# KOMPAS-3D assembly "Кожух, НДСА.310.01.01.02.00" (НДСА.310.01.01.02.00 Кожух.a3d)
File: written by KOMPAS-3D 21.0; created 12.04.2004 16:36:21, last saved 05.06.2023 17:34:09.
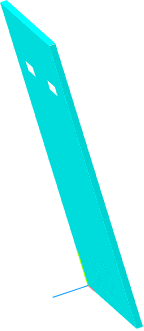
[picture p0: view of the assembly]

Document properties: Полное имя файла: C:\PLM\НДСА.310.01.01.02.00 Кожух.a3d

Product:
- Part/product: Кожух  | designation НДСА.310.01.01.02.00
    Масса: 6.188608
    additional columns: <item xmlns="http://appius.ru/pdm" xmlns:xs="http://www.w3.org/2001/XMLSchema" x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; <item xmlns="http://appius.ru/pdm" xmlns:xs="http://www.w3.org/2001/XMLSchema" x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; <item xmlns="http://appius.ru/pdm" xmlns:xs="http://www.w3.org/2001/XMLSchema" x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; <item xmlns="http://appius.ru/pdm" xmlns:xs="http://www.w3.org/2001/XMLSchema" x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; <item xmlns="http://appius.ru/pdm" xmlns:xs="http://www.w3.org/2001/XMLSchema" x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; <item xmlns="http://appius.ru/pdm" xmlns:xs="http://www.w3.org/2001/XMLSchema" x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; <item xmlns="http://appius.ru/pdm" xmlns:xs="http://www.w3.org/2001/XMLSchema" x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; <item xmlns="http://appius.ru/pdm" xmlns:xs="http://www.w3.org/2001/XMLSchema" x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
    source file: НДСА.310.01.01.02.00 Кожух.spw
  - Component [detail]: Крышка  | designation НДСА.310.01.01.02.01  | pos. 1  | Масса: 5.766009; Раздел спецификации: Детали; Форматы листов документа: A2; additional columns: <item xmlns="http://appius.ru/pdm" xmlns:xs="http://www.w3.org/2001/XMLSchema" x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; <item xmlns="http://appius.ru/pdm" xmlns:xs="http://www.w3.org/2001/XMLSchema" x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; <item xmlns="http://appius.ru/pdm" xmlns:xs="http://www.w3.org/2001/XMLSchema" x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; <item xmlns="http://appius.ru/pdm" xmlns:xs="http://www.w3.org/2001/XMLSchema" x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; <item xmlns="http://appius.ru/pdm" xmlns:xs="http://www.w3.org/2001/XMLSchema" x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; <item xmlns="http://appius.ru/pdm" xmlns:xs="http://www.w3.org/2001/XMLSchema" x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; <item xmlns="http://appius.ru/pdm" xmlns:xs="http://www.w3.org/2001/XMLSchema" x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; <item xmlns="http://appius.ru/pdm" xmlns:xs="http://www.w3.org/2001/XMLSchema" x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; source file: НДСА.310.01.01.02.01 Крышка.CDW, НДСА.310.01.01.02.01 Крышка.m3d
  - Component [detail]: Стяжка  | designation НДСА.875.03.00.00.02  | pos. 2  | Масса: 0.4226; Раздел спецификации: Детали; Форматы листов документа: A4; additional columns: <item xmlns="http://appius.ru/pdm" xmlns:xs="http://www.w3.org/2001/XMLSchema" x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; <item xmlns="http://appius.ru/pdm" xmlns:xs="http://www.w3.org/2001/XMLSchema" x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; <item xmlns="http://appius.ru/pdm" xmlns:xs="http://www.w3.org/2001/XMLSchema" x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; <item xmlns="http://appius.ru/pdm" xmlns:xs="http://www.w3.org/2001/XMLSchema" x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; <item xmlns="http://appius.ru/pdm" xmlns:xs="http://www.w3.org/2001/XMLSchema" x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; <item xmlns="http://appius.ru/pdm" xmlns:xs="http://www.w3.org/2001/XMLSchema" x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; <item xmlns="http://appius.ru/pdm" xmlns:xs="http://www.w3.org/2001/XMLSchema" x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; <item xmlns="http://appius.ru/pdm" xmlns:xs="http://www.w3.org/2001/XMLSchema" x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; source file: НДСА.875.03.00.00.02 Стяжка.cdw, НДСА.875.03.00.00.02 Стяжка.m3d

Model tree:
1. Фронтальная плоскость
2. Горизонтальная плоскость
3. Профильная плоскость
4. Начало координат  (with: Сгиб:4, Сгиб:2, Листовое тело:1)  (labels: Листовое тело:1; Листовое тело:1; Листовое тело:1)
     Расстояние = 20; Расстояние = 371.5

Referenced files in C:\PLM\: НДСА.310.01.01.02.01 Крышка.m3d, НДСА.310.01.01.02.01 Крышка.CDW, НДСА.875.03.00.00.02 Стяжка.m3d, НДСА.875.03.00.00.02 Стяжка.cdw
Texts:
  НДСА.310.01.01.02.01
  НДСА.875.03.00.00.02
  НДСА.310.01.01.02.00
  НДСА.310.01.01.02.01 Крышка
  НДСА.875.03.00.00.02 Стяжка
